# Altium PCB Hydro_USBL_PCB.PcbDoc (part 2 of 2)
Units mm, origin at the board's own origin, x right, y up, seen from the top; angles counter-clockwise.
Board outline 75 x 75 mm, 4 copper layers (Top Layer, Layer 1, Layer 2, Bottom Layer), stack 0.871 mm thick; 273 components, 152 nets, 824 pads, 165 vias.
Unrouted connection lines stored in the file: 155.
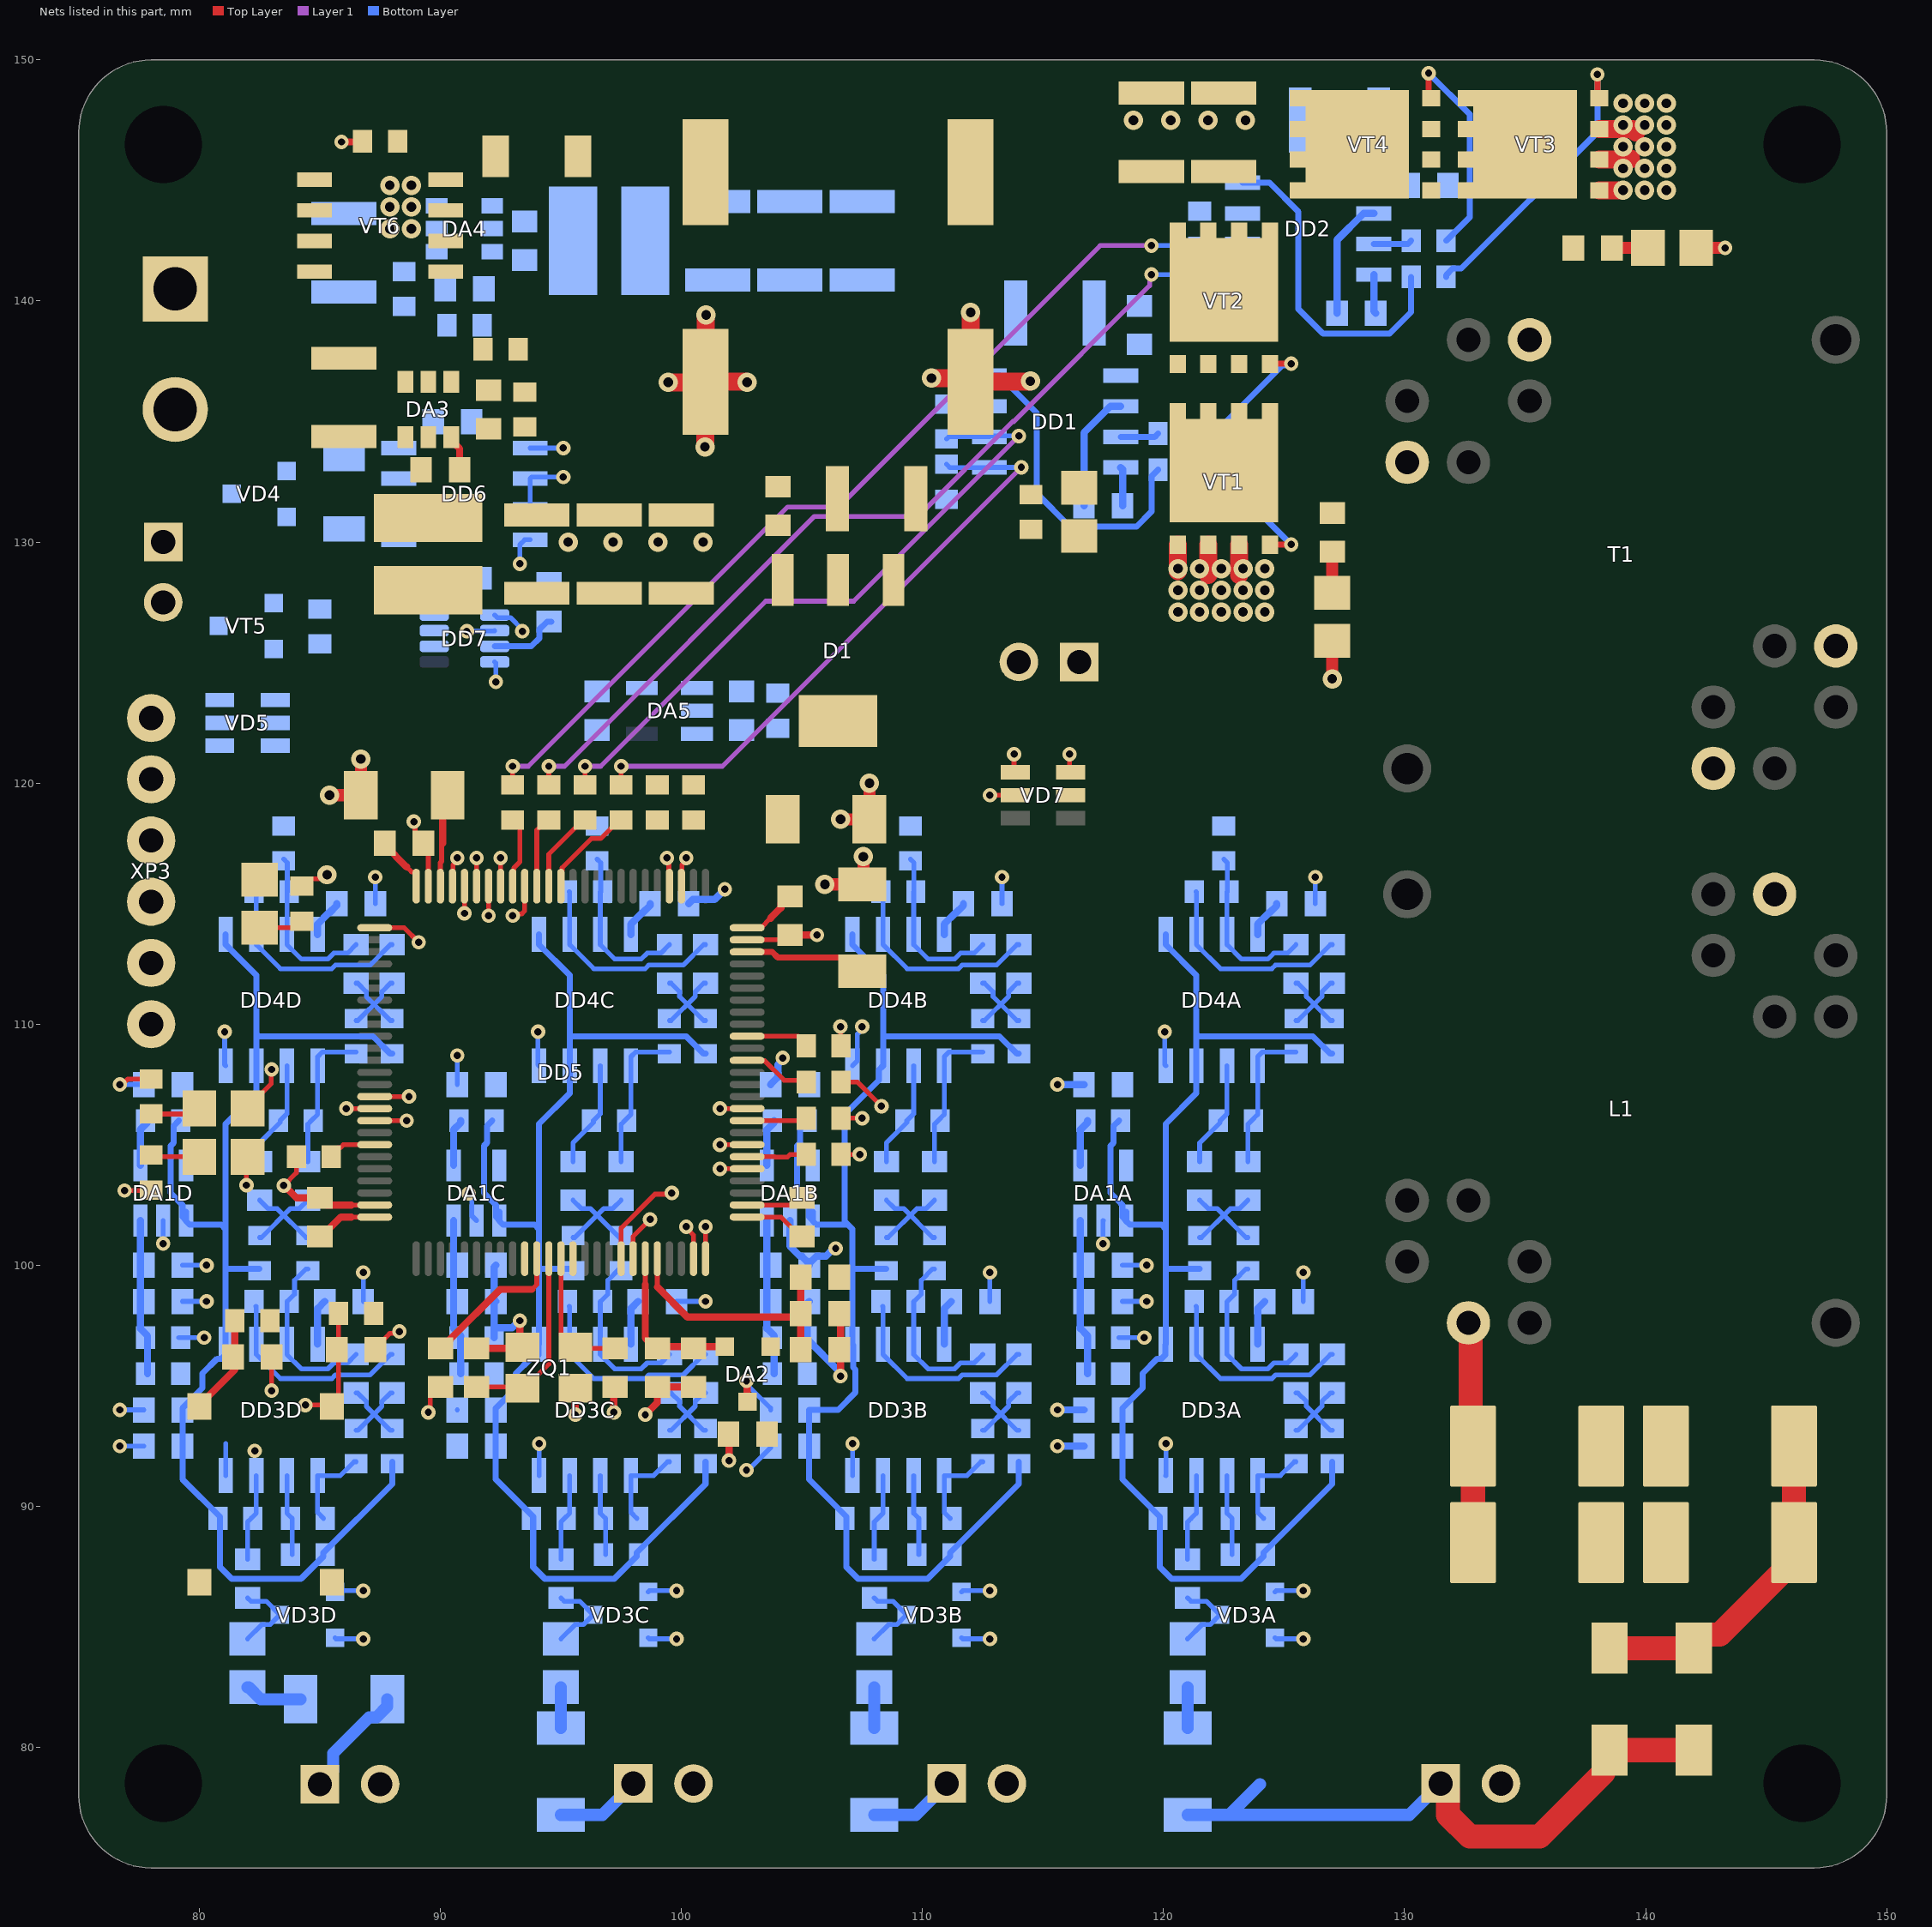
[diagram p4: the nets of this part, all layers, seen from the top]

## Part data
C1 C3 C8 C11 C51 C56 C60: library part Capacitor_10u_10_35V_X7R_1210C, "Конденсатор 1210C ёмкостью 10 мк 10%, 35 В, X7R", Capacity (nF)=10000, Dielectric=X7R, Tolerance=10%, Voltage (V)=35
C2 C4 C12 C22A C22B C22C C22D C23A C23B C23C C23D C24A C24B C24C C24D C28A C28B C28C C28D C31A C31B C31C C31D C36 C37 C38 C39 C42 C43 C44 C49 C50 C52 C53 C61 C67: library part Capacitor_0,1u_10_50V_X7R_0603C, "Конденсатор 0603C ёмкостью 0,1 мк 10%, 50 В, X7R", Capacity (nF)=100, Dielectric=X7R, Tolerance=10%, Voltage (V)=50
C5 C6 C40 C41 C59 C63: library part Capacitor_1u_10_25V_X7R_0603C, "Конденсатор 0603C ёмкостью 1 мк 10%, 25 В, X7R", Capacity (nF)=1000, Dielectric=X7R, Tolerance=10%, Voltage (V)=25
C7 C9: library part 50SVPF68M, "Конденсатор алюминиевый полимерный 68мкФ 50В ±20% (10х12.6мм) для поверхностного монтажа 0.02Ом 4300мА 5000час 105°С", Capacity (uF)=68, Tolerance=20, Voltage (V)=50
C10 C15 C20A C20B C20C C20D: library part Capacitor_1n_5_50V_NP0_0603C, "Конденсатор 0603C ёмкостью 1 н 5%, 50 В, NP0", Capacity (nF)=1, Dielectric=NP0, Tolerance=5%, Voltage (V)=50
C19A C19B C19C C19D: library part Capacitor_100p_5_630V_NP0_1206C, "Конденсатор 1206C ёмкостью 100 п 5%, 630 В, NP0", Capacity (nF)=0,1, Dielectric=NP0, Tolerance=5%, Voltage (V)=630
C21A C21B C21C C21D C27A C27B C27C C27D: library part Capacitor_10u_10_10V_X7R_0603C, "Конденсатор 0603C ёмкостью 10 мк 10%, 10 В, X7R", Capacity (nF)=10000, Dielectric=X7R, Tolerance=10%, Voltage (V)=10
C25A C25B C25C C25D C26A C26B C26C C26D C29A C29B C29C C29D C30A C30B C30C C30D C32A C32B C32C C32D C33A C33B C33C C33D C54 C62: library part Capacitor_3.3n_5_50V_NP0_0603C, "Конденсатор 0603C ёмкостью 3,3 н 5%, 50 В, NP0", Capacity (nF)=3,3, Dielectric=NP0, Tolerance=5%, Voltage (V)=50
C34: library part Capacitor_4,7u_10_50V_X7R_1206C, "Конденсатор 1206C ёмкостью 4,7 мк 10%, 50 В, X7R", Capacity (nF)=4700, Dielectric=X7R, Tolerance=10%, Voltage (V)=50
C35: library part Capacitor_0,47u_10_50V_X7R_0603C, "Конденсатор 0603C ёмкостью 0,47 мк 10%, 50 В, X7R", Capacity (nF)=470, Dielectric=X7R, Tolerance=10%, Voltage (V)=50
C45 C46: library part Capacitor_2,2u_10_50V_X7R_1206C, "Конденсатор 1206C ёмкостью 2,2 мк 10%, 50 В, X7R", Capacity (nF)=2200, Dielectric=X7R, Tolerance=10%, Voltage (V)=50
C47 C48: library part Capacitor_12p_5_50V_NP0_0603C, "Конденсатор 0603C ёмкостью 12 п 5%, 50 В, NP0", Capacity (nF)=0,012, Dielectric=NP0, Tolerance=5%, Voltage (V)=50
C55 C57 C58 C64 C65 C66: library part Capacitor_22u_10_25V_X7R_1210C, "Конденсатор 1210C ёмкостью 22 мк 10%, 25 В, X7R", Capacity (nF)=22000, Dielectric=X7R, Tolerance=10%, Voltage (V)=25
D1: "Линейный стабилизатор напряжения"
DA1A DA1B DA1C DA1D: "Операционный усилитель, 80МГц, 1-канал, 35В/мкс, Voltage Feedback, Rail-to-Rail"
DA2: "Источник опорного напряжения, 3В"
DA3 DA4: "DC-DC понижающий преобразователь, Vin: 3.8 - 40 В, adj, 2 А"
DA5: "Стабилизатор напряжения 3.3В 150мА"
DD1 DD2: "Полумостовой драйвер затвора для mosfet транзисторов"
DD3A DD3B DD3C DD3D DD4A DD4B DD4C DD4D: "Операционный усилитель 28МГц, CMOS, 2-канала, Rail-to-Rail"
DD5: "Микроконтроллер, 32-Бит, Cortex-M7, 480МГц, 2Мб Flash, 1Мб SRAM, 82 I/O", Package="LQFP-100 STMicroelectronics"
DD6: "RS-485 приёмопередатчик"
DD7: "CAN трансивер 1Mbps +3.3В"
FB1: "Дроссель подавления ЭМП"
HL1 HL2 HL3 HL4: "Светодиод"
L1: "Индуктивность на сердечнике RM8"
L2 L3: "Индуктивность на 15 мкГн, номинальный ток 1,3 А", Current="1,3 А", Inductance (μH)=15
R1 R2 R3 R4 R19A R19B R19C R19D R20A R20B R20C R20D R32 R41 R46 R49 R53 R54: library part Resistor_10k_1_0603, "Резистор номиналом 10 кОм 1%", Tolerance=1%
R5 R6 R7 R8 R57: library part Resistor_3.3_1_0603, "Резистор номиналом 3,3 Ом 1%", Tolerance=1%
R9 R10: library part Resistor_47_1_0805, "Резистор номиналом 47 Ом 1%", Tolerance=1%
R11 R12 R13 R14: library part Resistor_33_1_2512, "Резистор номиналом 33 Ом 1%", Tolerance=1%
R15A R15B R15C R15D: library part Resistor_1k_0805, "Резистор номиналом 1 кОм 1%", Tolerance=1%
R16A R16B R16C R16D R44 R45 R47 R50 R52: library part Resistor_1.0k_1_0603, "Резистор номиналом 1,0 кОм 1%", Tolerance=1%
R17A R17B R17C R17D: library part Resistor_470k_1_0603, "Резистор номиналом 470 кОм 1%", Tolerance=1%
R18A R18B R18C R18D: library part Resistor_12k_1_0603, "Резистор номиналом 12 кОм 1%", Tolerance=1%
R21A R21B R21C R21D: library part Resistor_8.2k_1_0603, "Резистор номиналом 8,2 кОм 1%", Tolerance=1%
R22A R22B R22C R22D: library part Resistor_620_1_0603, "Резистор номиналом 620 Ом 1%", Tolerance=1%
R23A R23B R23C R23D R24A R24B R24C R24D: library part Resistor_4.7k_1_0603, "Резистор номиналом 4,7 кОм 1%", Tolerance=1%
R25A R25B R25C R25D R28A R28B R28C R28D: library part Resistor_560_1_0603, "Резистор номиналом 560 Ом 1%", Tolerance=1%
R26A R26B R26C R26D R31A R31B R31C R31D: library part Resistor_220_1_0603, "Резистор номиналом 220 Ом 1%", Tolerance=1%
R27A R27B R27C R27D: library part Resistor_6.2k_1_0603, "Резистор номиналом 6,2 кОм 1%", Tolerance=1%
R29A R29B R29C R29D: library part Resistor_1.5k_1_0603, "Резистор номиналом 1,5 кОм 1%", Tolerance=1%
R30A R30B R30C R30D: library part Resistor_16k_1_0603, "Резистор номиналом 16 кОм 1%", Tolerance=1%
R33 R34 R35 R36 R37 R38 R39 R40: library part Resistor_200_1_0603, "Резистор номиналом 200 Ом 1%", Tolerance=1%
R42 R43: library part Resistor_0_5_0603, "Резистор номиналом 0 Ом 5%", Tolerance=5%
R48: library part Resistor_5.1k_1_0603, "Резистор номиналом 5,1 кОм 1%", Tolerance=1%
R51: library part Resistor_11k_1_0603, "Резистор номиналом 11 кОм 1%", Tolerance=1%
R55: library part Resistor_120_1_1206, "Резистор номиналом 120 Ом 1%", Tolerance=1%
R56: library part Resistor_100k_1_0603, "Резистор номиналом 100 кОм 1%", Tolerance=1%
S1 S2: "Тактовая кнопка"
T1: "Трансформатор на сердечнике RM8"
VD1 VD2: "Выпрямительный диод на 1000 В, ном. ток 1 А А", Current="1 А", Voltage (V)=1000
VD3A VD3B VD3C VD3D: "Диод импульсный, 2 х 0.2А, 70В, последовательное включение", Current=0.2, Voltage (V)=70
VD4: "Защитный диод для линии RS-485"
VD5 VD7: "Сборка защитных диодов для USB"
VD6: "Стабилитрон 12В, 5%, 0.5Вт", Current="5 мА", Power (W)=0.5, Voltage (V)=12
VT1 VT2 VT3 VT4: "N-канальный MOSFET, 60 В, 50 А", Current (A)="50 А", Voltage (V)="60 В"
VT5: "P-канальный MOSFET"
VT6: "P-канальный MOSFET, 30 В, 20 А", Current (A)="20 А", Voltage (V)="30 В"
XP1: "2-пиновый разъем с ключом", Value1="эта плюс", Value2="это пинус"
XP2: "2-пиновый разъем с ключом", Value1=B, Value2=A
XP3: "Гребенка 6 пинов", Value1=+3,3В, Value2=SWDIO, Value3=SWCLK, Value4=GND, Value5=UART_TX, Value6=UART_RX
XP4: "2-пиновый разъем с ключом", Value1=DM, Value2=DP
XP5: "2-пиновый разъем с ключом", Value1=ANT1, Value2=GND
XP6: "2-пиновый разъем с ключом", Value1=ANT2, Value2=GND
XP7: "2-пиновый разъем с ключом", Value1=ANT3, Value2=GND
XP8: "2-пиновый разъем с ключом", Value1=ANT4, Value2=GND
ZQ1: "Кварцевый резонатор SMD 25 МГц ±10ppm SMD-3225_4P"

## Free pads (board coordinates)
  round 1.524 hole 3.2 unplated: 1(78.5,78.5) 1(78.5,146.5) 1(146.5,146.5) 1(146.5,78.5)

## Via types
v1: diameter 0.6, hole 0.3, Top Layer to Bottom Layer, tented both sides, 106 vias
v2: diameter 0.8, hole 0.4, Top Layer to Bottom Layer, tented both sides, 59 vias

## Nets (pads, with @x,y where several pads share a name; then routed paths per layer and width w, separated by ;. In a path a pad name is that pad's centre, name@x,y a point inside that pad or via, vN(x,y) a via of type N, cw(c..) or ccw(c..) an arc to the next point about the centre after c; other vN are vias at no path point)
+5В: C12.2 C52.2 C54.2 C55.2 C57.2 C58.2 C59.2 C67.1 D1.3 DA5.1 DD6.8 DD7.3 L2.2 R48.2 R49.2 | length 3
  Bottom Layer w0.25: DD7.3@92.255,125.675 93.775,125.675 94.1,126 94.1,126.375 94.425,126.7 C12.2@94.6,126.7
+10В: C1.1 C2.2 C3.1 C4.2 C62.2 C64.2 C65.2 C66.2 DD1.1 DD2.1 HL4.1 L3.2 R51.1
+24В: C7.1 C8.2 C9.1 C11.2 C51.2 C60.2 DA3.2 DA3.3 DA4.2 DA4.3 VD6.2 VT2.5 VT4.5 VT6.1 VT6.2 VT6.3
  other v2: 87.9,143 88.8,143 87.9,143.9 88.8,143.9 87.9,144.8 88.8,144.8
ADC1: DD5.30 R31A.2 | length 1.1
  Top Layer w0.2: v1(101.6,104) DD5.30@102.725,104
ADC2: DD5.32 R31B.2 | length 1.1
  Top Layer w0.2: v1(101.6,105) DD5.32@102.725,105
ADC3: DD5.35 R31C.2 | length 1.1
  Top Layer w0.2: v1(101.6,106.5) DD5.35@102.725,106.5
ADC4: DD5.18 R31D.2 | length 4
  Top Layer w0.2: DD5.18@97.5,100.275 97.5,101.549 98.9,102.949 99.549,102.949 v1(99.6,103)
ANT1: C19A.1 VD1.2 VD2.1 XP5.1 | length 26.7
  Top Layer w1: XP5.1@131.5,78.5 131.8,78.2 131.8,77.2 132.7,76.3 135.6,76.3 138.25,78.95 138.25,79.635 VD1.2@138.5,79.885 VD2.1@142,79.885
  Bottom Layer w0.5: C19A.1@121,77.2 122.725,77.2 ; 124,78.475 122.725,77.2 ; XP5.1@131.475,78.475 130.2,77.2 122.725,77.2
ANT2: C19B.1 XP6.1 | length 3.5
  Bottom Layer w0.5: C19B.1@108,77.2 109.725,77.2 XP6.1@111,78.475
ANT3: C19C.1 XP7.1 | length 3.5
  Bottom Layer w0.5: C19C.1@95,77.2 96.725,77.2 XP7.1@98,78.475
ANT4: C19D.1 XP8.1 | length 4.9
  Bottom Layer w0.5: XP8.1@85,78.475 85.55,79.025 85.55,79.75 87.05,81.25 87.35,81.25 87.8,81.7 C19D.1@87.8,82
BUTTON_4: C49.2 DD5.92 R41.1 S1.1 | length 5.5
  Top Layer w0.2: DD5.92@87.275,106 v1(88.6,106)
  Top Layer w0.3: S1.1@80,94.15 80,94.2 81.475,95.675 R41.1@81.475,97.7
CAN_RX: DD5.70 DD7.1 | length 2.6
  Top Layer w0.2: DD5.70@91.5,115.725 v1(91.5,116.9)
  Bottom Layer w0.2: DD7.1@92.255,126.975 92.365,126.865 92.914,126.865 93.4,126.379 v1(93.4,126.3)
CAN_TX: DD5.71 DD7.4 | length 2
  Top Layer w0.2: v1(91,114.6) DD5.71@91,115.725
  Bottom Layer w0.2: DD7.4@92.255,125.025 92.3,124.98 v1(92.3,124.2)
GND: C1.2 C2.1 C3.2 C4.1 C7.2 C8.1 C9.2 C11.1 C12.1 C21A.1 C21B.1 C21C.1 C21D.1 C22A.1 C22B.1 C22C.1 C22D.1 C23A.1 C23B.1 C23C.1 C23D.1 C24A.1 C24B.1 C24C.1 C24D.1 C27A.1 C27B.1 C27C.1 C27D.1 C28A.1 C28B.1 C28C.1 C28D.1 C31A.1 C31B.1 C31C.1 C31D.1 C34.1 C35.1 C36.1 C37.1 C38.1 C39.1 C40.1 C41.1 C42.1 C43.1 C44.1 C45.1 C46.1 C47.1 C48.1 C49.1 C50.1 C51.1 C52.1 C55.1 C56.1 C57.1 C58.1 C59.1 C60.1 C63.1 C64.1 C65.1 C66.1 C67.2 D1.1 DA1A.2 DA1B.2 DA1C.2 DA1D.2 DA2.3 DA3.4 DA4.4 DA5.2 DD1.7 DD2.7 DD3A.4 DD3B.4 DD3C.4 DD3D.4 DD4A.4 DD4B.4 DD4C.4 DD4D.4 DD5.10 DD5.19 DD5.26 DD5.49 DD5.74 DD5.99 DD6.5 DD7.2 R1.1 R2.1 R3.1 R4.1 R9.1 R10.1 R19A.1 R19B.1 R19C.1 R19D.1 R32.1 R44.1 R45.1 R47.1 R50.1 R52.1 R53.1 R54.1 R56.1 R57.1 S1.2 S2.2 T1.11 VD3A.1 VD3A.2 VD3B.1 VD3B.2 VD3C.1 VD3C.2 VD3D.1 VD3D.2 VD4.3 VD5.2 VD7.2 VT1.1 VT1.2 VT1.3 VT3.1 VT3.2 VT3.3 XP1.N XP3.4 XP5.2 XP6.2 XP7.2 XP8.2 ZQ1.2 ZQ1.4 | length 137.3
  Top Layer w0.2: v1(76.7,107.5) 76.808,107.5 77.033,107.725 R44.1@78,107.725 ; v1(76.9,103.1) 77.975,103.1 R45.1@78,103.125 ; v1(83,94.8) C49.1@83,96.2 ; v1(83.5,103.306) 84.025,103.831 R32.1@84.025,104.5 ; R52.1@84.25,115.725 84.55,116.025 84.963,116.025 85.138,116.2 v2(85.3,116.2) ; 86.3,102.5 DD5.99@87.275,102.5 ; C50.1@87.3,96.5 87.3,96.575 87.898,97.173 88.223,97.173 v1(88.3,97.25) ; v1(88.9,118.4) 88.95,118.35 88.95,117.85 89.5,117.3 DD5.74@89.5,115.725 ; v1(89.5,93.9) 89.575,93.975 89.575,94.6 89.925,94.95 C37.1@90,94.95 ; DD5.19@98,100.275 98,101.2 v1(98.7,101.9) ; DA2.3@102.7,94.386 DA2.3@102.748,94.339 ; DD5.26@102.725,102 104.125,102 104.925,101.2 C36.1@105,101.2 ; DD5.49@102.725,113.5 104.3,113.5 C42.1@104.5,113.7 ; v1(112.8,119.5) VD7.2@113.85,119.5
  Top Layer w0.3: v1(83.5,103.306) 83.519,103.306 84.025,102.8 C38.1@85,102.8 85.3,102.5 86.3,102.5 ; v1(85.9,146.6) 86.75,146.6 R56.1@86.775,146.625 ; C48.1@91.5,96.55 93.35,96.55 ZQ1.2@93.4,96.6 93.3,96.7 v1(93.3,97.7) ; v1(95.6,93.8) ZQ1.4@95.6,94.9 ; v1(97.2,93.9) 97.2,94.9 C47.1@97.25,94.95 ; v1(98.5,93.8) 99,94.3 C41.1@99,94.95 C44.1@100.5,94.95 ; C35.1@101.95,93 101.975,92.975 v1(101.975,91.9) ; DA2.3@102.7,94.386 102.724,94.41 102.724,95.176 v1(102.7,95.2) ; C42.1@104.5,113.7 v1(105.625,113.7) ; C43.1@106.55,98 106.6,97.95 v1(106.6,95.4)
  Top Layer w0.5: v2(85.4,119.5) C45.1@86.7,119.5 v2(86.7,121) ; v2(105.95,115.8) C46.1@107.5,115.8 107.55,115.85 v2(107.55,116.95) ; v2(106.6,118.5) C34.1@107.8,118.5 v2(107.8,120) ; v2(127,124.325) R9.1@127,125.9 ; R10.1@142.1,142.2 v1(143.3,142.2)
  Top Layer w0.75: v2(99.45,136.625) 100.975,136.625 C7.2@100.985,136.635 ; v2(100.975,133.95) 100.985,133.96 C7.2@100.985,136.635 ; v2(101.025,139.425) 101.015,139.415 101.015,136.665 C7.2@101,136.65 ; v2(102.725,136.625) 102.711,136.625 102.686,136.65 C7.2@101,136.65 ; v2(110.375,136.8) 111.85,136.8 C9.2@112,136.65 ; v2(112,139.525) C9.2@112,136.65 ; v2(114.475,136.675) 114.461,136.675 114.436,136.65 C9.2@112,136.65 ; v2@120.588,128.788 VT1.1@120.588,129.888 ; 121.863,128.637 VT1.2@121.863,129.888 ; v2@123.138,128.638 VT1.3@123.138,129.888 ; VT3.1@138.075,144.588 138.078,144.59 139.053,144.59 v2(139.063,144.6) ; VT3.2@138.075,145.863 139.363,145.863 139.4,145.9 ; VT3.3@138.075,147.138 139.462,147.138 139.6,147 ; C7.2@100.985,136.635 C7.2@101,136.65
  Bottom Layer w0.2: v1(76.7,92.5) C28D.1@77.7,92.5 ; v1(76.7,94) C27D.1@77.7,94 ; v1(76.7,107.5) C23D.1@77.7,107.5 ; v1(78.5,100.9) DA1D.2@78.5,101.855 ; R19D.1@79.15,97 v1(80.2,97) ; C22D.1@79.3,98.5 v1(80.3,98.5) ; C21D.1@79.3,100 v1(80.3,100) ; v1(81.052,109.684) 81.052,108.318 DD4D.4@81.095,108.275 ; DD3D.4@81.095,91.275 81.1,91.28 81.1,92.6 ; VD3D.2@85.625,84.545 85.67,84.5 v1(86.8,84.5) ; VD3D.1@85.625,86.45 85.675,86.5 v1(86.8,86.5) ; C24D.1@86.8,98.5 v1(86.8,99.7) ; C31D.1@87.3,115 v1(87.3,116.1) ; C23C.1@90.7,107.5 v1(90.7,108.7) ; v1(91.1,126.3) 91.113,126.312 92.242,126.312 DD7.2@92.255,126.325 ; v1(91.175,102.975) 91.175,102.867 91.305,102.737 91.305,102.05 DA1C.2@91.5,101.855 ; v1(94.052,109.684) 94.052,108.318 DD4C.4@94.095,108.275 ; DD3C.4@94.095,91.275 94.1,91.28 v1(94.1,92.6) ; VD3C.2@98.625,84.545 98.67,84.5 v1(99.8,84.5) ; VD3C.1@98.625,86.45 98.675,86.5 v1(99.8,86.5) ; C24C.1@99.8,98.5 v1(101,98.5) ; v1(102.7,91.5) 102.775,91.5 103.7,92.425 C28B.1@103.7,92.5 ; v1(102.7,95.2) 102.777,95.123 102.777,94.998 103.7,94.075 C27B.1@103.7,94 ; DD3B.4@107.095,91.275 107.1,91.28 v1(107.1,92.6) ; DD4B.4@107.095,108.275 107.295,108.475 107.295,109.587 107.5,109.792 v1(107.5,109.9) ; VD3B.2@111.625,84.545 111.67,84.5 v1(112.8,84.5) ; VD3B.1@111.625,86.45 111.675,86.5 v1(112.8,86.5) ; C24B.1@112.8,98.5 v1(112.8,99.7) ; C31B.1@113.3,115 v1(113.3,116.1) ; v1(117.491,100.891) 117.495,100.895 117.495,101.85 DA1A.2@117.5,101.855 ; R19A.1@118.15,97 v1(119.2,97) ; C22A.1@118.3,98.5 v1(119.3,98.5) ; C21A.1@118.3,100 v1(119.3,100) ; v1(120.052,109.684) 120.052,108.318 DD4A.4@120.095,108.275 ; DD3A.4@120.095,91.275 120.1,91.28 v1(120.1,92.6) ; VD3A.2@124.625,84.545 124.67,84.5 v1(125.8,84.5) ; VD3A.1@124.625,86.45 124.675,86.5 v1(125.8,86.5) ; C24A.1@125.8,98.5 v1(125.8,99.7) ; C31A.1@126.3,115 v1(126.3,116.1)
  Bottom Layer w0.3: R19C.1@92.225,97 R19C.1@92.225,97.4 ; C22C.1@92.225,98.5 92.225,99.925 C21C.1@92.3,100 ; C22C.1@92.3,98.5 92.225,98.425 R19C.1@92.225,97.4 ; v1(93.3,97.7) 93.274,97.7 92.974,97.4 R19C.1@92.225,97.4 ; C31C.1@100.3,115 100.476,115.176 101.376,115.176 v1(101.8,115.6) ; C23B.1@103.7,107.5 104,107.8 104,108.319 104.2,108.519 v1(104.2,108.6) ; DA1B.2@104.5,101.855 104.5,100.8 104.925,100.375 105,100.375 C21B.1@105.3,100.075 ; R19B.1@105.225,96.925 106.543,95.607 106.543,95.457 v1(106.6,95.4) ; R19B.1@105.225,97 105.225,98.425 C22B.1@105.3,98.5 ; C21B.1@105.3,100 C21B.1@105.3,100.075 ; v1(106.4,100.7) 106.319,100.7 105.994,100.375 105.6,100.375 C21B.1@105.3,100.075 ; v1(115.6,92.5) C28A.1@116.7,92.5 ; v1(115.6,94) C27A.1@116.7,94 ; v1(115.6,107.5) C23A.1@116.7,107.5
  other v1: 82.3,92.3
  other v2: 120.6,127.1 121.5,127.1 122.4,127.1 123.3,127.1 124.2,127.1 120.6,128 121.5,128 122.4,128 123.3,128 124.2,128 120.6,128.9 121.5,128.9 122.4,128.9 123.3,128.9 124.2,128.9 95.3,130 97.167,130 99.033,130 100.9,130 139.963,144.6 140.863,144.6 139.063,145.5 139.963,145.5 140.863,145.5 139.063,146.4 139.963,146.4 140.863,146.4 139.063,147.3 139.963,147.3 140.863,147.3 118.75,147.5 120.3,147.5 121.85,147.5 123.4,147.5 139.063,148.2 139.963,148.2 140.863,148.2
HRTIM_CHA1_4: DD5.63 R33.1 | length 4.1
  Top Layer w0.2: DD5.63@95,115.725 95.019,115.744 95.019,116.346 95.05,116.377 95.05,116.486 96.264,117.7 96.65,117.7 97.425,118.475 R33.1@97.5,118.475
HRTIM_CHA2_4: DD5.64 R34.1 | length 3.4
  Top Layer w0.2: DD5.64@94.5,115.725 94.5,117.05 95.925,118.475 R34.1@96,118.475
HRTIM_CHB1_4: DD5.65 R35.1 | length 3
  Top Layer w0.2: DD5.65@94,115.725 94,118.05 94.425,118.475 R35.1@94.5,118.475
HRTIM_CHB2_4: DD5.67 R36.1 | length 3
  Top Layer w0.2: DD5.67@93,115.725 93,116.327 93.05,116.377 93.05,116.486 93.3,116.736 93.3,118.175 R36.1@93,118.475
LED1_4: DD5.90 HL1.1 | length 3.5
  Top Layer w0.2: HL1.1@82,106.5 82,106.55 82.975,107.525 82.975,108.1 v1(83,108.125) ; DD5.90@87.275,107 v1(88.7,107)
LED2_4: DD5.91 HL2.1 | length 2.4
  Top Layer w0.2: v1(81.953,103.321) 81.953,104.453 HL2.1@82,104.5 ; v1(86.1,106.5) DD5.91@87.275,106.5
NetC5_1: C5.1 DD1.2 | length 5
  Bottom Layer w0.3: C5.1@116.7,131.5 116.7,134.535 117.8,135.635 DD1.2@118.225,135.635
NetC5_2: C5.2 C10.2 DD1.4 T1.2 VT1.5 VT2.1 VT2.2 VT2.3 | length 1.6
  Bottom Layer w0.3: DD1.4@118.225,133.095 118.3,133.02 C5.2@118.3,131.5
NetC6_1: C6.1 DD2.2 | length 5
  Bottom Layer w0.3: C6.1@127.2,139.5 127.2,142.535 128.3,143.635 DD2.2@128.725,143.635
NetC6_2: C6.2 C15.2 DD2.4 T1.5 VT3.5 VT4.1 VT4.2 VT4.3 | length 1.6
  Bottom Layer w0.3: DD2.4@128.725,141.095 128.725,139.575 C6.2@128.8,139.5
NetC10_1: C10.1 R9.2 | length 1.7
  Top Layer w0.5: R9.2@127,127.6 C10.1@127,129.3
NetC15_1: C15.1 R10.2 | length 1.5
  Top Layer w0.5: C15.1@138.6,142.2 R10.2@140.1,142.2
NetC19A_2: C19A.2 R15A.1 | length 1.7
  Bottom Layer w0.5: C19A.2@121,80.8 R15A.1@121,82.5
NetC19B_2: C19B.2 R15B.1 | length 1.7
  Bottom Layer w0.5: C19B.2@108,80.8 R15B.1@108,82.5
NetC19C_2: C19C.2 R15C.1 | length 1.7
  Bottom Layer w0.5: C19C.2@95,80.8 R15C.1@95,82.5
NetC19D_2: C19D.2 R15D.1 | length 2.4
  Bottom Layer w0.5: R15D.1@82,82.5 82.05,82.5 82.55,82 C19D.2@84.2,82
NetC20A_1: C20A.1 R15A.2 VD3A.3 | length 3.4
  Bottom Layer w0.2: R15A.2@121,84.5 121.6,85.1 121.941,85.1 VD3A.3@122.339,85.497 121.775,86.061 121.139,86.061 C20A.1@121,86.2
NetC20A_2: C20A.2 DD3A.3 R17A.2 | length 3.6
  Bottom Layer w0.2: C20A.2@121,87.8 121,89.35 121.15,89.5 121.365,89.715 DD3A.3@121.365,91.275
NetC20B_1: C20B.1 R15B.2 VD3B.3 | length 3.4
  Bottom Layer w0.2: R15B.2@108,84.5 108.6,85.1 108.941,85.1 VD3B.3@109.339,85.497 108.775,86.061 108.139,86.061 C20B.1@108,86.2
NetC20B_2: C20B.2 DD3B.3 R17B.2 | length 3.6
  Bottom Layer w0.2: C20B.2@108,87.8 108,89.35 108.15,89.5 108.365,89.715 DD3B.3@108.365,91.275
NetC20C_1: C20C.1 R15C.2 VD3C.3 | length 3.4
  Bottom Layer w0.2: R15C.2@95,84.5 95.6,85.1 95.941,85.1 VD3C.3@96.339,85.497 95.775,86.061 95.139,86.061 C20C.1@95,86.2
NetC20C_2: C20C.2 DD3C.3 R17C.2 | length 3.6
  Bottom Layer w0.2: C20C.2@95,87.8 95,89.35 95.15,89.5 95.365,89.715 DD3C.3@95.365,91.275
NetC20D_1: C20D.1 R15D.2 VD3D.3 | length 3.4
  Bottom Layer w0.2: R15D.2@82,84.5 82.6,85.1 82.942,85.1 VD3D.3@83.339,85.497 82.775,86.061 82.139,86.061 C20D.1@82,86.2
NetC20D_2: C20D.2 DD3D.3 R17D.2 | length 3.6
  Bottom Layer w0.2: C20D.2@82,87.8 82,89.35 82.15,89.5 82.365,89.715 DD3D.3@82.365,91.275
NetC21A_2: C21A.2 C22A.2 DA1A.3 R18A.1 R19A.2 | length 6.5
  Bottom Layer w0.3: DA1A.3@116.55,101.855 116.55,97.375 116.85,97.075 R18A.1@116.85,95.5
NetC21B_2: C21B.2 C22B.2 DA1B.3 R18B.1 R19B.2 | length 6.5
  Bottom Layer w0.3: DA1B.3@103.55,101.855 103.55,97.375 103.85,97.075 103.85,97 R18B.1@103.85,95.5
NetC21C_2: C21C.2 C22C.2 DA1C.3 R18C.1 R19C.2 | length 6.5
  Bottom Layer w0.3: DA1C.3@90.55,101.855 90.55,97.375 90.85,97.075 90.85,97 R18C.1@90.85,95.5
NetC21D_2: C21D.2 C22D.2 DA1D.3 R18D.1 R19D.2 | length 6.5
  Bottom Layer w0.3: DA1D.3@77.55,101.855 77.55,97.375 77.85,97.075 77.85,97 R18D.1@77.85,95.5
NetC25A_1: C25A.1 C26A.1 R21A.1 R22A.2 | length 4.5
  Bottom Layer w0.2: R22A.2@125.5,93.15 125.575,93.15 126.575,94.15 126.575,94.35 126.925,94.7 C26A.1@127,94.7 ; C25A.1@125.5,94.7 125.575,94.7 125.925,94.35 125.925,94.15 126.925,93.15 R21A.1@127,93.15
NetC25A_2: C25A.2 DD3A.7 R24A.1 R25A.1 | length 7.3
  Bottom Layer w0.2: R25A.1@123.5,99.85 123.425,99.85 122.95,99.375 122.95,98.8 122.65,98.5 122.635,98.485 DD3A.7@122.635,96.725 122.635,96.3 123.235,95.7 124.329,95.7 124.579,95.95 125.15,95.95 C25A.2@125.5,96.3
NetC25B_1: C25B.1 C26B.1 R21B.1 R22B.2 | length 4.5
  Bottom Layer w0.2: R22B.2@112.5,93.15 112.575,93.15 113.575,94.15 113.575,94.35 113.925,94.7 C26B.1@114,94.7 ; C25B.1@112.5,94.7 112.575,94.7 112.925,94.35 112.925,94.15 113.925,93.15 R21B.1@114,93.15
NetC25B_2: C25B.2 DD3B.7 R24B.1 R25B.1 | length 7.3
  Bottom Layer w0.2: R25B.1@110.5,99.85 110.425,99.85 109.95,99.375 109.95,98.8 109.65,98.5 109.635,98.485 DD3B.7@109.635,96.725 109.635,96.3 110.235,95.7 111.329,95.7 111.579,95.95 112.15,95.95 C25B.2@112.5,96.3
NetC25C_1: C25C.1 C26C.1 R21C.1 R22C.2 | length 4.5
  Bottom Layer w0.2: R22C.2@99.5,93.15 99.575,93.15 100.575,94.15 100.575,94.35 100.925,94.7 C26C.1@101,94.7 ; C25C.1@99.5,94.7 99.575,94.7 99.925,94.35 99.925,94.15 100.925,93.15 R21C.1@101,93.15
NetC25C_2: C25C.2 DD3C.7 R24C.1 R25C.1 | length 7.3
  Bottom Layer w0.2: R25C.1@97.5,99.85 97.425,99.85 96.95,99.375 96.95,98.8 96.65,98.5 96.635,98.485 DD3C.7@96.635,96.725 96.635,96.3 97.235,95.7 98.329,95.7 98.579,95.95 99.15,95.95 C25C.2@99.5,96.3
NetC25D_1: C25D.1 C26D.1 R21D.1 R22D.2 | length 4.5
  Bottom Layer w0.2: R22D.2@86.5,93.15 86.575,93.15 87.575,94.15 87.575,94.35 87.925,94.7 C26D.1@88,94.7 ; C25D.1@86.5,94.7 86.575,94.7 86.925,94.35 86.925,94.15 87.925,93.15 R21D.1@88,93.15
NetC25D_2: C25D.2 DD3D.7 R24D.1 R25D.1 | length 7.3
  Bottom Layer w0.2: R25D.1@84.5,99.85 84.425,99.85 83.95,99.375 83.95,98.8 83.65,98.5 83.635,98.485 DD3D.7@83.635,96.725 83.635,96.3 84.235,95.7 85.329,95.7 85.579,95.95 86.15,95.95 C25D.2@86.5,96.3
NetC26A_2: C26A.2 DD3A.6 R24A.2 | length 8.5
  Bottom Layer w0.2: R24A.2@121.35,98.3 121.365,98.285 121.365,96.3 122.365,95.3 124.497,95.3 124.647,95.45 126.075,95.45 126.925,96.3 C26A.2@127,96.3
NetC26B_2: C26B.2 DD3B.6 R24B.2 | length 8.5
  Bottom Layer w0.2: R24B.2@108.35,98.3 108.365,98.285 108.365,96.3 109.365,95.3 111.497,95.3 111.647,95.45 113.075,95.45 113.925,96.3 C26B.2@114,96.3
NetC26C_2: C26C.2 DD3C.6 R24C.2 | length 8.5
  Bottom Layer w0.2: R24C.2@95.35,98.3 95.365,98.285 95.365,96.3 96.365,95.3 98.497,95.3 98.647,95.45 100.075,95.45 100.925,96.3 C26C.2@101,96.3
NetC26D_2: C26D.2 DD3D.6 R24D.2 | length 8.5
  Bottom Layer w0.2: R24D.2@82.35,98.3 82.365,98.285 82.365,96.3 83.365,95.3 85.497,95.3 85.647,95.45 87.075,95.45 87.925,96.3 C26D.2@88,96.3
NetC29A_1: C29A.1 C30A.1 R25A.2 R26A.2 | length 5.3
  Bottom Layer w0.2: R26A.2@121.5,101.15 121.575,101.15 122.775,102.35 123.15,102.35 C29A.1@123.5,102.7 ; C30A.1@121.5,102.7 121.85,102.35 122.225,102.35 123.425,101.15 R25A.2@123.5,101.15
NetC29A_2: C29A.2 DD4A.1 R27A.2 R29A.1 | length 6.2
  Bottom Layer w0.2: C29A.2@123.5,104.3 123.5,105.85 123.65,106 123.905,106.255 DD4A.1@123.905,108.275 123.905,108.65 124.105,108.85 R29A.1@125.5,108.85
NetC29B_1: C29B.1 C30B.1 R25B.2 R26B.2 | length 5.3
  Bottom Layer w0.2: R26B.2@108.5,101.15 108.575,101.15 109.775,102.35 110.15,102.35 C29B.1@110.5,102.7 ; C30B.1@108.5,102.7 108.85,102.35 109.225,102.35 110.425,101.15 R25B.2@110.5,101.15
NetC29B_2: C29B.2 DD4B.1 R27B.2 R29B.1 | length 6.2
  Bottom Layer w0.2: C29B.2@110.5,104.3 110.5,105.85 110.65,106 110.905,106.255 DD4B.1@110.905,108.275 110.905,108.65 111.105,108.85 R29B.1@112.5,108.85
NetC29C_1: C29C.1 C30C.1 R25C.2 R26C.2 | length 5.3
  Bottom Layer w0.2: R26C.2@95.5,101.15 95.575,101.15 96.775,102.35 97.15,102.35 C29C.1@97.5,102.7 ; C30C.1@95.5,102.7 95.85,102.35 96.225,102.35 97.425,101.15 R25C.2@97.5,101.15
NetC29C_2: C29C.2 DD4C.1 R27C.2 R29C.1 | length 6.2
  Bottom Layer w0.2: C29C.2@97.5,104.3 97.5,105.85 97.65,106 97.905,106.255 DD4C.1@97.905,108.275 97.905,108.65 98.105,108.85 R29C.1@99.5,108.85
NetC29D_1: C29D.1 C30D.1 R25D.2 R26D.2 | length 5.3
  Bottom Layer w0.2: R26D.2@82.5,101.15 82.575,101.15 83.775,102.35 84.15,102.35 C29D.1@84.5,102.7 ; C30D.1@82.5,102.7 82.85,102.35 83.225,102.35 84.425,101.15 R25D.2@84.5,101.15
NetC29D_2: C29D.2 DD4D.1 R27D.2 R29D.1 | length 6.2
  Bottom Layer w0.2: C29D.2@84.5,104.3 84.5,105.85 84.65,106 84.905,106.255 DD4D.1@84.905,108.275 84.905,108.65 85.105,108.85 R29D.1@86.5,108.85
NetC30A_2: C30A.2 DD4A.2 R27A.1 | length 4.4
  Bottom Layer w0.2: C30A.2@121.5,104.3 121.5,105.075 122.35,105.925 122.35,106 122.635,106.285 DD4A.2@122.635,108.275
NetC30B_2: C30B.2 DD4B.2 R27B.1 | length 4.4
  Bottom Layer w0.2: C30B.2@108.5,104.3 108.5,105.075 109.35,105.925 109.35,106 109.635,106.285 DD4B.2@109.635,108.275
NetC30C_2: C30C.2 DD4C.2 R27C.1 | length 4.4
  Bottom Layer w0.2: C30C.2@95.5,104.3 95.5,105.075 96.35,105.925 96.35,106 96.635,106.285 DD4C.2@96.635,108.275
NetC30D_2: C30D.2 DD4D.2 R27D.1 | length 4.4
  Bottom Layer w0.2: C30D.2@82.5,104.3 82.5,105.075 83.35,105.925 83.35,106 83.635,106.285 DD4D.2@83.635,108.275
NetC32A_1: C32A.1 C33A.1 R28A.2 R29A.2 | length 4.5
  Bottom Layer w0.2: R29A.2@125.5,110.15 125.575,110.15 126.575,111.15 126.575,111.35 126.925,111.7 C33A.1@127,111.7 ; C32A.1@125.5,111.7 125.575,111.7 125.925,111.35 125.925,111.15 126.925,110.15 R28A.2@127,110.15
NetC32A_2: C32A.2 DD4A.7 R30A.2 R31A.1 | length 7
  Bottom Layer w0.2: R31A.1@122.5,116.85 122.65,116.7 122.65,115.5 122.635,115.485 DD4A.7@122.635,113.725 122.635,113.3 123.235,112.7 124.329,112.7 124.579,112.95 125.15,112.95 C32A.2@125.5,113.3
NetC32B_1: C32B.1 C33B.1 R28B.2 R29B.2 | length 4.5
  Bottom Layer w0.2: R29B.2@112.5,110.15 112.575,110.15 113.575,111.15 113.575,111.35 113.925,111.7 C33B.1@114,111.7 ; C32B.1@112.5,111.7 112.575,111.7 112.925,111.35 112.925,111.15 113.925,110.15 R28B.2@114,110.15
NetC32B_2: C32B.2 DD4B.7 R30B.2 R31B.1 | length 7
  Bottom Layer w0.2: R31B.1@109.5,116.85 109.65,116.7 109.65,115.5 109.635,115.485 DD4B.7@109.635,113.725 109.635,113.3 110.235,112.7 111.329,112.7 111.579,112.95 112.15,112.95 C32B.2@112.5,113.3
NetC32C_1: C32C.1 C33C.1 R28C.2 R29C.2 | length 4.5
  Bottom Layer w0.2: R29C.2@99.5,110.15 99.575,110.15 100.575,111.15 100.575,111.35 100.925,111.7 C33C.1@101,111.7 ; C32C.1@99.5,111.7 99.575,111.7 99.925,111.35 99.925,111.15 100.925,110.15 R28C.2@101,110.15
NetC32C_2: C32C.2 DD4C.7 R30C.2 R31C.1 | length 7
  Bottom Layer w0.2: R31C.1@96.5,116.85 96.65,116.7 96.65,115.5 96.635,115.485 DD4C.7@96.635,113.725 96.635,113.3 97.235,112.7 98.329,112.7 98.579,112.95 99.15,112.95 C32C.2@99.5,113.3
NetC32D_1: C32D.1 C33D.1 R28D.2 R29D.2 | length 4.5
  Bottom Layer w0.2: R29D.2@86.5,110.15 86.575,110.15 87.575,111.15 87.575,111.35 87.925,111.7 C33D.1@88,111.7 ; C32D.1@86.5,111.7 86.575,111.7 86.925,111.35 86.925,111.15 87.925,110.15 R28D.2@88,110.15
NetC32D_2: C32D.2 DD4D.7 R30D.2 R31D.1 | length 7
  Bottom Layer w0.2: R31D.1@83.5,116.85 83.65,116.7 83.65,115.5 83.635,115.485 DD4D.7@83.635,113.725 83.635,113.3 84.235,112.7 85.329,112.7 85.579,112.95 86.15,112.95 C32D.2@86.5,113.3
NetC33A_2: C33A.2 DD4A.6 R30A.1 | length 8.7
  Bottom Layer w0.2: R30A.1@121.35,115.5 121.365,115.485 DD4A.6@121.365,113.725 121.365,113.3 122.365,112.3 124.495,112.3 124.645,112.45 126.075,112.45 126.925,113.3 C33A.2@127,113.3
NetC33B_2: C33B.2 DD4B.6 R30B.1 | length 8.7
  Bottom Layer w0.2: R30B.1@108.35,115.5 108.365,115.485 DD4B.6@108.365,113.725 108.365,113.3 109.365,112.3 111.495,112.3 111.645,112.45 113.075,112.45 113.925,113.3 C33B.2@114,113.3
NetC33C_2: C33C.2 DD4C.6 R30C.1 | length 8.7
  Bottom Layer w0.2: R30C.1@95.35,115.5 95.365,115.485 DD4C.6@95.365,113.725 95.365,113.3 96.365,112.3 98.495,112.3 98.645,112.45 100.075,112.45 100.925,113.3 C33C.2@101,113.3
NetC33D_2: C33D.2 DD4D.6 R30D.1 | length 8.7
  Bottom Layer w0.2: R30D.1@82.35,115.5 82.365,115.485 DD4D.6@82.365,113.725 82.365,113.3 83.365,112.3 85.495,112.3 85.645,112.45 87.075,112.45 87.925,113.3 C33D.2@88,113.3
NetC40_2: C40.2 C43.2 DD5.21 FB1.2 | length 10.7
  Top Layer w0.2: 99,99.1 DD5.21@99,100.275
  Top Layer w0.3: 99,99.1 100.25,97.85 104.8,97.85 C43.2@104.95,98 ; C40.2@104.95,96.5 104.95,97.85 C43.2@104.95,98 ; FB1.2@104.95,99.5 C43.2@104.95,98
NetC45_2: C45.2 DD5.73 | length 3.9
  Top Layer w0.2: DD5.73@90,115.725 90,116.7 90.05,116.75 90.05,117.45 90.1,117.5
  Top Layer w0.3: 90.1,117.5 90.1,119.3 C45.2@90.3,119.5
NetC46_2: C46.2 DD5.48 | length 5.1
  Top Layer w0.25: DD5.48@102.725,113 103.765,113 103.99,112.775 106.925,112.775 C46.2@107.5,112.2
NetC47_2: C47.2 DD5.13 ZQ1.1 | length 5.7
  Top Layer w0.2: DD5.13@95,100.275 95,97.1 95.5,96.6 ZQ1.1@95.6,96.6 95.65,96.55 C47.2@97.25,96.55
NetC48_2: C48.2 DD5.12 ZQ1.3 | length 7.8
  Top Layer w0.2: C48.2@91.5,94.95 93.45,94.95 93.5,94.9 94.5,95.9 DD5.12@94.5,100.275
NetC53_1: C53.1 DA3.6 | length 1.5
  Top Layer w0.3: DA3.6@90.45,134.35 90.45,134.223 90.622,134.05 90.624,134.05 90.8,133.874 C53.1@90.8,133
NetC53_2: C53.2 DA3.5 L2.1
NetC54_1: C54.1 DA3.1 R47.2 R48.1
NetC61_1: C61.1 DA4.6
NetC61_2: C61.2 DA4.5 L3.1
NetC62_1: C62.1 DA4.1 R50.2 R51.2
NetDA1A_4: DA1A.4 R23A.1 | length 2
  Bottom Layer w0.3: DA1A.4@116.55,104.145 116.55,105.625 116.85,105.925 R23A.1@116.85,106
NetDA1B_4: DA1B.4 R23B.1 | length 2
  Bottom Layer w0.3: DA1B.4@103.55,104.145 103.55,105.625 103.85,105.925 R23B.1@103.85,106
NetDA1C_4: DA1C.4 R23C.1 | length 2
  Bottom Layer w0.3: DA1C.4@90.55,104.145 90.55,105.625 90.85,105.925 R23C.1@90.85,106
NetDA1D_4: DA1D.4 R23D.1 | length 2
  Bottom Layer w0.3: DA1D.4@77.55,104.145 77.55,105.625 77.85,105.925 R23D.1@77.85,106
NetDA5_3: DA5.3 R49.1
NetDD1_3: DD1.3 R5.1 | length 1.6
  Bottom Layer w0.25: DD1.3@118.225,134.365 119.64,134.365 R5.1@119.775,134.5
NetDD1_8: DD1.8 R6.1 | length 13.4
  Bottom Layer w0.25: DD1.8@112.775,136.905 113.2,136.905 114.745,135.36 114.745,132.02 116.115,130.65 118.885,130.65 119.5,131.265 119.5,132.725 R6.1@119.775,133
NetDD2_3: DD2.3 R7.1 | length 1.6
  Bottom Layer w0.25: DD2.3@128.725,142.365 130.14,142.365 R7.1@130.275,142.5
NetDD2_8: DD2.8 R8.1 | length 13.8
  Bottom Layer w0.25: DD2.8@123.275,144.905 124.395,144.905 125.6,143.7 125.6,139.665 126.615,138.65 129.385,138.65 130.275,139.54 R8.1@130.275,141
NetDD3A_1: DD3A.1 R20A.2 R22A.1 | length 3.7
  Bottom Layer w0.2: R20A.2@124.15,89.5 123.905,89.745 DD3A.1@123.905,91.275 124.85,91.275 125.425,91.85 R22A.1@125.5,91.85
NetDD3A_2: DD3A.2 R16A.2 R20A.1 | length 3.4
  Bottom Layer w0.2: DD3A.2@122.635,91.275 122.635,89.715 122.85,89.5 R16A.2@122.85,88
NetDD3B_1: DD3B.1 R20B.2 R22B.1 | length 3.7
  Bottom Layer w0.2: R20B.2@111.15,89.5 110.905,89.745 DD3B.1@110.905,91.275 111.85,91.275 112.425,91.85 R22B.1@112.5,91.85
NetDD3B_2: DD3B.2 R16B.2 R20B.1 | length 3.4
  Bottom Layer w0.2: DD3B.2@109.635,91.275 109.635,89.715 109.85,89.5 R16B.2@109.85,88
NetDD3C_1: DD3C.1 R20C.2 R22C.1 | length 3.7
  Bottom Layer w0.2: R20C.2@98.15,89.5 97.905,89.745 DD3C.1@97.905,91.275 98.85,91.275 99.425,91.85 R22C.1@99.5,91.85
NetDD3C_2: DD3C.2 R16C.2 R20C.1 | length 3.4
  Bottom Layer w0.2: DD3C.2@96.635,91.275 96.635,89.715 96.85,89.5 R16C.2@96.85,88
NetDD3D_1: DD3D.1 R20D.2 R22D.1 | length 3.7
  Bottom Layer w0.2: R20D.2@85.15,89.5 84.905,89.745 DD3D.1@84.905,91.275 85.85,91.275 86.425,91.85 R22D.1@86.5,91.85
NetDD3D_2: DD3D.2 R16D.2 R20D.1 | length 3.4
  Bottom Layer w0.2: DD3D.2@83.635,91.275 83.635,89.715 83.85,89.5 R16D.2@83.85,88
NetDD5_94: DD5.94 R32.2 | length 2.1
  Top Layer w0.2: R32.2@85.475,104.5 85.475,104.575 85.775,104.875 85.85,104.875 85.975,105 DD5.94@87.275,105
NetDD7_8: DD7.8 R57.2
NetHL1_2: HL1.2 R44.2 | length 2.1
  Top Layer w0.2: R44.2@78,106.275 79.775,106.275 HL1.2@80,106.5
NetHL2_2: HL2.2 R45.2 | length 2
  Top Layer w0.2: R45.2@78,104.575 78.075,104.5 HL2.2@80,104.5
NetHL3_2: HL3.2 R52.2 | length 1.9
  Top Layer w0.2: HL3.2@82.5,114 83.975,114 R52.2@84.25,114.275
NetHL4_2: HL4.2 R53.2
NetL1_3: L1.3 T1.8
NetL1_9: L1.9 R11.1 R12.1 | length 9.2
  Top Layer w1: L1.9@132.65,97.61 132.745,97.515 132.745,92.595 R11.1@132.84,92.5 R12.1@132.84,88.5
NetR5_2: R5.2 VT2.4 | length 6.2
  Top Layer w0.25: VT2.4@124.413,137.388 124.425,137.4 v1(125.3,137.4)
  Bottom Layer w0.25: R5.2@121.225,134.5 122.1,134.5 124.933,137.333 125.233,137.333 v1(125.3,137.4)
NetR6_2: R6.2 VT1.4 | length 6.3
  Top Layer w0.25: VT1.4@124.413,129.888 124.425,129.9 v1(125.3,129.9)
  Bottom Layer w0.25: R6.2@121.225,133 122.2,133 v1(125.3,129.9)
NetR7_2: R7.2 VT4.4 | length 9.1
  Top Layer w0.25: v1(131,149.45) 131,148.525 VT4.4@131.113,148.413
  Bottom Layer w0.25: v1(131,149.45) 132.7,147.75 132.7,143.475 R7.2@131.725,142.5
NetR8_2: R8.2 VT3.4 | length 12.2
  Top Layer w0.25: v1(138,149.4) 138,148.488 VT3.4@138.075,148.413
  Bottom Layer w0.25: R8.2@131.725,141 131.725,141.075 132,141.35 132.35,141.35 138,147 v1(138,149.4)
NetR11_2: R11.2 R12.2 R13.1 R14.1
NetR13_2: R13.2 R14.2 VD1.1 VD2.2 | length 13.8
  Top Layer w1: VD1.1@138.5,84.115 VD2.2@142,84.115 ; VD2.2@142,84.425 142.25,84.675 143.07,84.675 146.16,87.765 R14.2@146.16,88.5 R13.2@146.16,92.5
NetR54_2: R54.2 VT5.1
NetR56_2: R56.2 VD6.1 VT6.4
NetVT5_3: VT5.3 XP3.1
NetVT6_5: VT6.5 VT6.6 VT6.7 VT6.8 XP1.P
PWM1_HI: DD1.5 R3.2 R33.2 R37.2 R43.2 | length 27.8
  Top Layer w0.2: R33.2@97.5,119.925 v1(97.5,120.7) ; R37.2@106.625,107.6 107.3,107.6 v1(108.3,106.6)
  Layer 1 w0.2: v1(97.5,120.7) 101.7,120.7 v1(114.1,133.1)
  Bottom Layer w0.2: R3.2@111,133.225 111.13,133.095 DD1.5@112.775,133.095 112.78,133.1 v1(114.1,133.1)
PWM1_LO: DD1.6 R1.2 R34.2 R38.2 R42.2 | length 28.3
  Top Layer w0.2: R34.2@96,119.925 v1(96,120.7) ; R38.2@106.625,104.6 v1(107.4,104.6)
  Layer 1 w0.2: v1(96,120.7) 96.651,120.7 103.501,127.55 107.15,127.55 v1(114,134.4)
  Bottom Layer w0.2: R1.2@111,134.275 111.09,134.365 DD1.6@112.775,134.365 112.81,134.4 v1(114,134.4)
PWM2_HI: DD2.5 R4.2 R35.2 R39.2 R42.1 | length 39.1
  Top Layer w0.2: R35.2@94.5,119.925 v1(94.5,120.7) ; v1(106.6,109.9) 106.6,109.125 R39.2@106.625,109.1
  Layer 1 w0.2: v1(94.5,120.7) 95.151,120.7 105.511,131.059 109.811,131.059 113.751,135 113.79,135 119.423,140.634 119.423,141.023 v1(119.5,141.1)
  Bottom Layer w0.2: v1(119.5,141.1) 121.475,141.1 R4.2@121.5,141.075 121.52,141.095 DD2.5@123.275,141.095
PWM2_LO: DD2.6 R2.2 R36.2 R40.2 R43.1 | length 40.9
  Top Layer w0.2: R36.2@93,119.925 v1(93,120.7) ; R40.2@106.625,106.1 v1(107.5,106.1)
  Layer 1 w0.2: v1(93,120.7) 93.651,120.7 104.411,131.459 106.534,131.459 117.375,142.3 v1(119.5,142.3)
  Bottom Layer w0.2: v1(119.5,142.3) 121.475,142.3 R2.2@121.5,142.275 121.59,142.365 DD2.6@123.275,142.365
RE&DE: DD5.66 DD6.2 DD6.3 | length 4.3
  Top Layer w0.2: v1(93,114.5) 93.077,114.577 93.377,114.577 93.5,114.7 DD5.66@93.5,115.725
  Bottom Layer w0.2: DD6.3@93.725,131.365 DD6.2@93.725,132.635 93.79,132.7 v1(95.1,132.7)
RESET_4: C50.2 DD5.14 R46.1 S2.1 | length 5.1
  Top Layer w0.2: v1(84.4,94.2) 85.45,94.2 S2.1@85.5,94.15 85.775,94.425 R46.1@85.775,98
RS485_6_N: DD6.6 DD7.7 R55.1 VD4.2 XP2.2
RS485_6_P: DD6.7 DD7.6 R55.2 VD4.1 XP2.1
SWCLOCK: DD5.76 VD5.1 XP3.3 | length 2.1
  Top Layer w0.2: DD5.76@87.275,114 88.5,114 v1(89.1,113.4)
SWDIO: DD5.72 VD5.6 XP3.2 | length 1.3
  Top Layer w0.2: DD5.72@90.5,115.725 90.519,115.744 90.519,116.611 90.7,116.792 v1(90.7,116.9)
TIM1_CH1_4: DD5.39 R37.1 | length 2.8
  Top Layer w0.2: DD5.39@102.725,108.5 102.744,108.481 103.456,108.481 104.261,107.675 105.1,107.675 R37.1@105.175,107.6
TIM1_CH1N_4: DD5.31 R38.1 | length 2.5
  Top Layer w0.2: DD5.31@102.725,104.5 103.871,104.5 103.879,104.493 104.404,104.493 104.511,104.6 R38.1@105.175,104.6
TIM1_CH2_4: DD5.41 R39.1 | length 2.7
  Top Layer w0.2: DD5.41@102.725,109.5 104.85,109.5 105.175,109.175 R39.1@105.175,109.1
TIM1_CH2N_4: DD5.34 R40.1 | length 2.5
  Top Layer w0.2: DD5.34@102.725,106 105.075,106 R40.1@105.175,106.1
UART1_RX: DD5.69 DD6.1 | length 2.6
  Top Layer w0.2: v1(92,114.5) DD5.69@92,115.725
  Bottom Layer w0.2: DD6.1@93.725,133.905 93.73,133.9 v1(95.1,133.9)
UART1_TX: DD5.68 DD6.4 | length 2.5
  Top Layer w0.2: DD5.68@92.5,115.725 v1(92.5,116.9)
  Bottom Layer w0.2: v1(93.3,129.1) 93.3,129.895 93.5,130.095 DD6.4@93.725,130.095
UART2_RX: DD5.25 VD5.3 XP3.6 | length 1.3
  Top Layer w0.2: DD5.25@101,100.275 v1(101,101.6)
UART2_TX: DD5.24 VD5.4 XP3.5 | length 1.4
  Top Layer w0.2: v1(100.2,101.6) 100.2,101.551 100.5,101.251 DD5.24@100.5,100.275
USB_N: DD5.53 VD7.6 XP4.1 | length 2
  Top Layer w0.2: DD5.53@100,115.725 100.019,115.744 100.019,116.611 100.2,116.792 v1(100.2,116.9) ; v1(116.1,121.2) 116.1,120.5 VD7.6@116.15,120.45
USB_P: DD5.54 VD7.1 XP4.2 | length 2
  Top Layer w0.2: v1(99.4,116.9) 99.4,116.792 99.481,116.711 99.481,115.744 DD5.54@99.5,115.725 ; v1(113.8,121.2) 113.8,120.5 VD7.1@113.85,120.45
VDD: C34.2 C36.2 C37.2 C38.2 C39.2 C42.2 C56.2 D1.2 DD5.11 DD5.27 DD5.50 DD5.75 DD5.100 HL3.1 R41.2 R46.2 VD5.5 VD7.5 VT5.2 | length 16
  Top Layer w0.2: 86.3,102 DD5.100@87.275,102 ; 88.6,116.525 88.806,116.319 88.954,116.319 89,116.273 DD5.75@89,115.725 ; 93.8,99 94,99.2 DD5.11@94,100.275 ; DD5.27@102.725,102.5 104.7,102.5 C36.2@105,102.8 ; DD5.50@102.725,114 103.3,114 103.7,114.4
  Top Layer w0.3: C38.2@85,101.2 85.075,101.2 85.875,102 86.3,102 ; C39.2@87.7,117.5 87.7,117.425 88.6,116.525 ; C37.2@90,96.55 90.075,96.55 90.375,96.85 90.375,96.895 92.48,99 93.8,99 ; 103.7,114.4 104.125,114.825 104.125,115 104.425,115.3 C42.2@104.5,115.3
VDDA: C23A.2 C23B.2 C23C.2 C23D.2 C24A.2 C24B.2 C24C.2 C24D.2 C31A.2 C31B.2 C31C.2 C31D.2 C35.2 C63.2 DA1A.5 DA1B.5 DA1C.5 DA1D.5 DA2.1 DA5.5 DD3A.8 DD3B.8 DD3C.8 DD3D.8 DD4A.8 DD4B.8 DD4C.8 DD4D.8 FB1.1 R18A.2 R18B.2 R18C.2 R18D.2 | length 14.1
  Bottom Layer w0.3: DD3D.8@84.905,96.725 84.905,98.205 C24D.2@85.2,98.5 ; DD4D.8@84.905,113.725 84.905,114.15 85.38,114.625 85.4,114.625 85.7,114.925 C31D.2@85.7,115 ; DD3C.8@97.905,96.725 97.905,98.205 C24C.2@98.2,98.5 ; DD4C.8@97.905,113.725 97.905,114.15 98.38,114.625 98.4,114.625 98.7,114.925 C31C.2@98.7,115 ; DD3B.8@110.905,96.725 110.905,98.205 C24B.2@111.2,98.5 ; DD4B.8@110.905,113.725 110.905,114.15 111.38,114.625 111.4,114.625 111.7,114.925 C31B.2@111.7,115 ; DD3A.8@123.905,96.725 123.905,98.205 C24A.2@124.2,98.5 ; DD4A.8@123.905,113.725 123.905,114.15 124.38,114.625 124.4,114.625 124.7,114.925 C31A.2@124.7,115
VREF_MCU: C41.2 C44.2 DA2.2 DD5.20 | length 6.8
  Top Layer w0.2: 98.5,99.2 DD5.20@98.5,100.275
  Top Layer w0.3: 98.5,99.2 98.5,96.975 98.925,96.55 C41.2@99,96.55 99.075,96.625 DA2.2@101.795,96.625
VREFAA: C27A.2 C28A.2 DA1A.1 DD3A.5 DD4A.3 DD4A.5 R16A.1 R17A.1 R21A.2 R23A.2 R26A.1 R28A.1 | length 52.8
  Bottom Layer w0.25: R23A.2@118.15,106 117.93,105.78 117.93,105.075 117.805,104.95 117.805,103 118.102,102.702 118.102,102.698 118.305,102.495 DA1A.1@118.305,102.22 ; DA1A.1@118.305,102.15 118.305,102 DA1A.1@118.45,101.855 ; DA1A.1@118.45,102.22 DA1A.1@118.45,101.855 ; DD3A.5@120.07,96.7 120.07,96.275 119.92,96.125 119.741,96.125 119.133,95.517 119.133,94.908 118.3,94.075 C27A.2@118.3,94 C28A.2@118.3,92.5 118.3,91.125 119.85,89.575 119.85,87.48 120.33,87 123.225,87 124.15,87.925 124.15,88.075 127,90.925 R21A.2@127,91.85 ; DD3A.5@120.095,96.725 120.095,99.85 ; DD4A.5@120.095,113.725 120.095,113.3 121.365,112.03 121.365,109.6 ; R26A.1@121.5,99.85 120.095,99.85 ; R28A.1@127,108.775 126.925,108.775 126.2,109.5 121.465,109.5 121.365,109.6 ; DA1A.1@118.45,101.855 118.45,101.826 118.595,101.681 119.914,101.681 120.095,101.5 ; 120.095,99.85 120.095,101.5 ; 120.095,101.5 120.095,105.865 121.365,107.135 DD4A.3@121.365,108.275 121.365,109.6
VREFAB: C27B.2 C28B.2 DA1B.1 DD3B.5 DD4B.3 DD4B.5 R16B.1 R17B.1 R21B.2 R23B.2 R26B.1 R28B.1 | length 53.5
  Bottom Layer w0.25: R23B.2@105.15,106 104.93,105.78 104.93,105.075 104.805,104.95 104.805,103 105.102,102.702 105.102,102.698 105.305,102.495 DA1B.1@105.305,102.22 ; DA1B.1@105.305,102.15 105.305,102 DA1B.1@105.45,101.855 ; DA1B.1@105.45,102.22 DA1B.1@105.45,101.855 ; 106.914,101.681 105.595,101.681 105.45,101.826 DA1B.1@105.45,101.855 ; DD4B.5@107.095,113.725 107.095,113.3 108.365,112.03 108.365,109.6 ; R26B.1@108.5,99.85 107.095,99.85 ; R21B.2@114,91.85 114,90.925 111.15,88.075 111.15,87.925 110.225,87 107.33,87 106.85,87.48 106.85,89.575 105.3,91.125 C28B.2@105.3,92.5 C27B.2@105.3,94 106.5,94 107.225,94.725 107.225,95.659 107.129,95.755 107.129,96.691 DD3B.5@107.095,96.725 107.095,99.85 ; R28B.1@114,108.775 113.925,108.775 113.2,109.5 108.465,109.5 108.365,109.6 ; 107.095,99.85 107.095,101.5 106.775,101.82 106.775,106.259 108.19,107.674 108.19,108.1 DD4B.3@108.365,108.275 108.365,109.5 108.365,109.6
VREFAC: C27C.2 C28C.2 DA1C.1 DD3C.5 DD4C.3 DD4C.5 R16C.1 R17C.1 R21C.2 R23C.2 R26C.1 R28C.1 | length 52.8
  Bottom Layer w0.25: R23C.2@92.15,106 91.93,105.78 91.93,105.075 91.805,104.95 91.805,103 92.102,102.702 92.102,102.698 92.305,102.495 DA1C.1@92.305,102.22 ; DA1C.1@92.305,102.15 92.305,102 DA1C.1@92.45,101.855 ; DA1C.1@92.45,102.22 DA1C.1@92.45,101.855 ; DD3C.5@94.07,96.7 94.07,96.275 93.92,96.125 93.741,96.125 93.133,95.517 93.133,94.908 92.3,94.075 C27C.2@92.3,94 C28C.2@92.3,92.5 92.3,91.125 93.85,89.575 93.85,87.48 94.33,87 97.225,87 98.15,87.925 98.15,88.075 101,90.925 R21C.2@101,91.85 ; DD3C.5@94.095,96.725 94.095,99.85 ; DD4C.5@94.095,113.725 94.095,113.3 95.365,112.03 95.365,109.6 ; R26C.1@95.5,99.85 94.095,99.85 ; R28C.1@101,108.775 100.925,108.775 100.2,109.5 95.465,109.5 95.365,109.6 ; DA1C.1@92.45,101.855 92.45,101.826 92.595,101.681 93.914,101.681 94.095,101.5 ; 94.095,99.85 94.095,101.5 ; 94.095,101.5 94.095,105.865 95.365,107.135 DD4C.3@95.365,108.275 95.365,109.6
VREFAD: C27D.2 C28D.2 DA1D.1 DD3D.5 DD4D.3 DD4D.5 R16D.1 R17D.1 R21D.2 R23D.2 R26D.1 R28D.1 | length 52.8
  Bottom Layer w0.25: R23D.2@79.15,106 78.93,105.78 78.93,105.075 78.805,104.95 78.805,103 79.102,102.702 79.102,102.698 79.305,102.495 DA1D.1@79.305,102.22 ; DA1D.1@79.305,102.15 79.305,102 DA1D.1@79.45,101.855 ; DA1D.1@79.45,102.22 DA1D.1@79.45,101.855 ; DD3D.5@81.07,96.7 81.07,96.275 80.92,96.125 80.741,96.125 80.133,95.517 80.133,94.908 79.3,94.075 C27D.2@79.3,94 C28D.2@79.3,92.5 79.3,91.125 80.85,89.575 80.85,87.48 81.33,87 84.225,87 85.15,87.925 85.15,88.075 88,90.925 R21D.2@88,91.85 ; DD3D.5@81.095,96.725 81.095,99.85 ; DD4D.5@81.095,113.725 81.095,113.3 82.365,112.03 82.365,109.6 ; R26D.1@82.5,99.85 81.095,99.85 ; R28D.1@88,108.775 87.925,108.775 87.2,109.5 82.465,109.5 82.365,109.6 ; DA1D.1@79.45,101.855 79.45,101.826 79.595,101.681 80.914,101.681 81.095,101.5 ; 81.095,99.85 81.095,101.5 ; 81.095,101.5 81.095,105.865 82.365,107.135 DD4D.3@82.365,108.275 82.365,109.6
pads on no net: DA5.4 DD5.1 DD5.2 DD5.3 DD5.4 DD5.5 DD5.6 DD5.7 DD5.8 DD5.9 DD5.15 DD5.16 DD5.17 DD5.22 DD5.23 DD5.28 DD5.29 DD5.33 DD5.36 DD5.37 DD5.38 DD5.40 DD5.42 DD5.43 DD5.44 DD5.45 DD5.46 DD5.47 DD5.51 DD5.52 DD5.55 DD5.56 DD5.57 DD5.58 DD5.59 DD5.60 DD5.61 DD5.62 DD5.77 DD5.78 DD5.79 DD5.80 DD5.81 DD5.82 DD5.83 DD5.84 DD5.85 DD5.86 DD5.87 DD5.88 DD5.89 DD5.93 DD5.95 DD5.96 DD5.97 DD5.98 DD7.5 L1.1 L1.2 L1.4 L1.5 L1.6 L1.7 L1.8 L1.10 L1.11 L1.12 L1.G1 L1.G2 T1.1 T1.3 T1.4 T1.6 T1.7 T1.9 T1.10 T1.12 T1.G1 T1.G2 VD7.3 VD7.4

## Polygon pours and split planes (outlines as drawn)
+5В on Top Layer "+5В_L01_P012" (solid, pour order 12): 104.9,124 105.3,124.4 105.3,131.2 102.7,131.2 102.4,130.9 102.4,129.2 87.1,129.2 87.1,124
GND on Top Layer "GND_L01_P011" (solid, pour order 11): 92.6,129.6 101.5,129.6 101.5,131.6 92.6,131.6
NetC53_2 on Top Layer "NETC53_2_L01_P010" (solid, pour order 10): 90,132.325 90.325,132 91.725,132 91.75,131.975 91.75,130.2 87.3,130.2 87.25,130.25 87.25,132.025 88.75,133.525 88.95,133.525 89.1,133.675 89.1,134.9 89.9,134.9 89.9,133.7 90,133.6
+24В on Top Layer "+24В_L01_P005" (solid, pour order 5): 85.9,145.4 89.2,145.4 90.15,144.45 90.15,144.4 94.4,144.4 100,150 117.5,150 117.5,147 124.4,147 124.4,149.9 130.2,149.9 130.2,141.2 127.3,138.3 91,138.3 89.9,137.2 89.9,135.4 83.8,135.4 83.8,138.4 85.9,140.5
NetR11_2 on Top Layer "NETR11_2_L01_P009" (solid, pour order 9): 137.2,94.2 141.8,94.2 141.8,86.8 141.7,86.9 137.2,86.9
NetC6_2 on Top Layer "NETC6_2_L01_P008" (solid, pour order 8): 136.4,134.5 137.4,135.5 137.4,143.9 137.4,149.745 130.2,149.745 130.2,141 128.75,139.55 130.2,138.1 135.1,133.2
NetC5_2 on Top Layer "NETC5_2_L01_P007" (solid, pour order 7): 130,138.3 128.75,139.55 127.5,138.3 119.6,138.3 119.6,130.5 132.4,130.5 135.1,133.2
NetVT6_5 on Top Layer "NETVT6_5_L01_P003" (solid, remove dead copper, pour order 3): 85.7,140.6 83.2,138.1 77.1,138.1 77.1,142.5 77.8,143.2 80,145.4 85.7,145.4
GND on Top Layer "GND_L01_P004" (solid, pour order 4): 117.5,150 124.4,150 124.4,147 117.5,147
GND on Top Layer "GND_L01_P001" (solid, pour order 1): 138.663,143.9 141.463,143.9 141.463,148.7 138.663,148.7
GND on Top Layer "GND_L01_P000" (solid, pour order 0): 119.9,129.3 119.9,126.5 124.7,126.5 124.7,129.3
+5В on Bottom Layer "+5В_L04_P013" (solid, pour order 13): 93.9,127.1 93.9,127.2 94.1,127.3 104.6,127.3 105.6,126.3 105.6,123.1 101.8,123.1 101.4,123.5 101.4,123.6 100.1,123.6 98.5,125.2 93.9,125.2
+24В on Bottom Layer "+24В_L04_P006" (solid, pour order 6): 84,142.6 90.9,142.6 90.9,145.5 84,145.5
GND on Layer 2 "NONET_L03_P002" (solid, remove dead copper, shelved, pour order 2): 75,78 75,147 cw(c78,147) 78,150 147,150 cw(c147,147) 150,147 150,78 cw(c147,78) 147,75 78,75 cw(c78,78)

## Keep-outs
Keep-Out Layer:
  circle w0.1: c78.5,78.5 r3
  circle w0.1: c146.5,78.5 r3
  circle w0.1: c146.5,146.5 r3
  circle w0.1: c78.5,146.5 r3

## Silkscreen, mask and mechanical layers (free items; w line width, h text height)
Shape:
  the board outline again, w0.254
